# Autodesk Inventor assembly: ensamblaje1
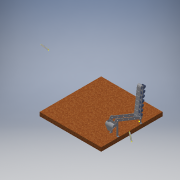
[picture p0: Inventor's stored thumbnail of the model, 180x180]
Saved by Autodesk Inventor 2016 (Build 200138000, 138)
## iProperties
Created: 2016-06
Part Number: ensamblaje1
Document SubType Name: Assembly
Designer: yesi alvarez
Mass: 32615.5 g
Surface Area: 17323.4 cm^2
Volume: 32615.5 cm^3
Density: 1 g/cm^3
Author: yesi alvarez
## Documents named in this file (13)
- C:\Users\adm\Desktop\proyecto del profe. valcarcel\ensamblaje1.iam
- C:\Users\adm\Desktop\proyecto del profe. valcarcel\tablero.ipt
- C:\Users\adm\Desktop\proyecto del profe. valcarcel\soporte1.ipt
- C:\Users\adm\Desktop\proyecto del profe. valcarcel\pieza que une los rodillos.ipt
- C:\Users\adm\Desktop\proyecto del profe. valcarcel\soporte2.ipt
- C:\Users\adm\Desktop\proyecto del profe. valcarcel\rodillo.ipt
- C:\Users\adm\Desktop\proyecto del profe. valcarcel\ensamblaje1\Design Accelerator\Bolted Connection3.iam
- C:\Users\adm\Desktop\proyecto del profe. valcarcel\tuerca.ipt
- C:\Users\adm\Desktop\proyecto del profe. valcarcel\faja2.ipt
- C:\Users\adm\Desktop\Alvarez\cangilogeno.ipt
- C:\Users\adm\Desktop\proyecto del profe. valcarcel\recepcion2.ipt
- C:\Users\adm\Desktop\proyecto del profe. valcarcel\trabajo3\eje.ipt
- C:\Users\adm\Desktop\proyecto del profe. valcarcel\trabajo3\159.iam
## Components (31 placed, 12 different names)
1. tablero:1 — Mate:1, Mate:4, Mate:16, Mate:19, Mate:66, Mate:67, Mate:68, Mate:69, Flush:3
2. soporte1:1 — Mate:1, Mate:2, Mate:3, Mate:20, Mate:21, Mate:44, Mate:45, Mate:46, Mate:57, Flush:2, Mate:68
3. soporte1:2 — Mate:17, Mate:18, Mate:19, Mate:49, Mate:50, Mate:55, Mate:56, Flush:2, Mate:69
4. pieza que une los rodillos:1 — Mate:2, Mate:3, Mate:5, Mate:6, Mate:7
5. pieza que une los rodillos:2 — Mate:13, Mate:14, Mate:15, Mate:17, Mate:18, Mate:65
6. soporte2:1 — Mate:4, Mate:5, Mate:6, Mate:47, Mate:48, Mate:58, Mate:59, Flush:1, Mate:66, Mate:86, Tangent:2
7. soporte2:2 — Mate:14, Mate:15, Mate:16, Mate:51, Mate:52, Mate:53, Mate:54, Flush:1, Mate:67, Flush:3, Mate:84, Mate:85, Tangente:3, Tangente:4
8. rodillo:1 — Mate:7, Mate:13, Mate:65, Flush:4, Flush:12, Tangente:6
9. Bolted Connection:1 [sub-assembly] — Mate:20, Mate:21
10. tuerca:11 — Mate:49, Mate:55
11. tuerca:12 — Mate:52, Mate:53
12. tuerca:13 — Mate:46, Mate:57
13. tuerca:14 — Mate:48, Mate:58
14. tuerca:15 — Mate:51, Mate:54
15. tuerca:16 — Mate:44, Mate:45
16. tuerca:17 — Mate:47, Mate:59
17. tuerca:18 — Mate:50, Mate:56
18. faja2:1 — Flush:4, Mate:70, Mate:71, Flush:5, Mate:72, Mate:73, Mate:74, Mate:75, Mate:76, Flush:6, Flush:7, Flush:8, Flush:9, Flush:10, Mate:77, Mate:78, Mate:79, Mate:80, Mate:81, Mate:82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
19. cangilogeno:1 — Mate:70, Mate:71, Flush:5
20. cangilogeno:2 — Mate:73, Flush:7, Mate:78
21. cangilogeno:3 — Mate:82, Mate:83, Flush:11
22. cangilogeno:4 — Mate:74, Flush:8, Mate:79
23. cangilogeno:5 — Mate:75, Flush:9, Mate:80
24. cangilogeno:6 — Mate:72, Flush:6, Mate:77
25. cangilogeno:7 — Mate:76, Flush:10, Mate:81
26. recepcion2:1 — Mate:84, Mate:85, Mate:86, Mate:87, Insert:2
27. tuerca:19 — Mate:87, Tangent:2
28. tuerca:20 — Insert:2
29. eje:1 — Coincidencia:88, Coincidencia:89, Nivelación:13, Coincidencia:90, Tangente:3, Tangente:4
30. eje:2 — Coincidencia:88, Coincidencia:89, Nivelación:13, Coincidencia:90, Tangente:5
31. 159:1 [sub-assembly]
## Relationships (77: Mate 58, Flush 13, Tangent 5, Insert 1)
- Mate:1: tablero:1 ↔ soporte1:1
- Mate:2: soporte1:1 ↔ pieza que une los rodillos:1
- Mate:3: soporte1:1 ↔ pieza que une los rodillos:1
- Mate:4: tablero:1 ↔ soporte2:1
- Mate:5: pieza que une los rodillos:1 ↔ soporte2:1
- Mate:6: pieza que une los rodillos:1 ↔ soporte2:1
- Mate:7: pieza que une los rodillos:1 ↔ rodillo:1
- Mate:13: pieza que une los rodillos:2 ↔ rodillo:1
- Mate:14: pieza que une los rodillos:2 ↔ soporte2:2
- Mate:15: pieza que une los rodillos:2 ↔ soporte2:2
- Mate:16: tablero:1 ↔ soporte2:2
- Mate:17: soporte1:2 ↔ pieza que une los rodillos:2
- Mate:18: soporte1:2 ↔ pieza que une los rodillos:2
- Mate:19: tablero:1 ↔ soporte1:2
- Mate:20: soporte1:1 ↔ Bolted Connection:1
- Mate:21: soporte1:1 ↔ Bolted Connection:1
- Mate:44: soporte1:1 ↔ tuerca:16
- Mate:45: soporte1:1 ↔ tuerca:16
- Mate:46: soporte1:1 ↔ tuerca:13
- Mate:47: soporte2:1 ↔ tuerca:17
- Mate:48: soporte2:1 ↔ tuerca:14
- Mate:49: soporte1:2 ↔ tuerca:11
- Mate:50: soporte1:2 ↔ tuerca:18
- Mate:51: soporte2:2 ↔ tuerca:15
- Mate:52: soporte2:2 ↔ tuerca:12
- Mate:53: soporte2:2 ↔ tuerca:12
- Mate:54: soporte2:2 ↔ tuerca:15
- Mate:55: soporte1:2 ↔ tuerca:11
- Mate:56: soporte1:2 ↔ tuerca:18
- Mate:57: soporte1:1 ↔ tuerca:13
- Mate:58: soporte2:1 ↔ tuerca:14
- Mate:59: soporte2:1 ↔ tuerca:17
- Mate:65: pieza que une los rodillos:2 ↔ rodillo:1
- Flush:1: soporte2:1 ↔ soporte2:2
- Flush:2: soporte1:1 ↔ soporte1:2
- Mate:66: tablero:1 ↔ soporte2:1
- Mate:67: tablero:1 ↔ soporte2:2
- Mate:68: tablero:1 ↔ soporte1:1
- Mate:69: tablero:1 ↔ soporte1:2
- Flush:3: tablero:1 ↔ soporte2:2
- Flush:4: rodillo:1 ↔ faja2:1
- Mate:70: faja2:1 ↔ cangilogeno:1
- Mate:71: faja2:1 ↔ cangilogeno:1
- Flush:5: faja2:1 ↔ cangilogeno:1
- Mate:72: faja2:1 ↔ cangilogeno:6
- Mate:73: faja2:1 ↔ cangilogeno:2
- Mate:74: faja2:1 ↔ cangilogeno:4
- Mate:75: faja2:1 ↔ cangilogeno:5
- Mate:76: faja2:1 ↔ cangilogeno:7
- Flush:6: faja2:1 ↔ cangilogeno:6
- Flush:7: faja2:1 ↔ cangilogeno:2
- Flush:8: faja2:1 ↔ cangilogeno:4
- Flush:9: faja2:1 ↔ cangilogeno:5
- Flush:10: faja2:1 ↔ cangilogeno:7
- Mate:77: faja2:1 ↔ cangilogeno:6
- Mate:78: faja2:1 ↔ cangilogeno:2
- Mate:79: faja2:1 ↔ cangilogeno:4
- Mate:80: faja2:1 ↔ cangilogeno:5
- Mate:81: faja2:1 ↔ cangilogeno:7
- Mate:82: faja2:1 ↔ cangilogeno:3
- Mate:83: faja2:1 ↔ cangilogeno:3
- Flush:11: faja2:1 ↔ cangilogeno:3
- Flush:12: rodillo:1 ↔ faja2:1
- Mate:84: soporte2:2 ↔ recepcion2:1
- Mate:85: soporte2:2 ↔ recepcion2:1
- Mate:86: soporte2:1 ↔ recepcion2:1
- Mate:87: recepcion2:1 ↔ tuerca:19
- Tangent:2: soporte2:1 ↔ tuerca:19
- Insert:2: recepcion2:1 ↔ tuerca:20
- Coincidencia:88 [Mate]: eje:1 ↔ eje:2
- Coincidencia:89 [Mate]: eje:1 ↔ eje:2
- Nivelación:13 [Flush]: eje:1 ↔ eje:2
- Coincidencia:90 [Mate]: eje:1 ↔ eje:2
- Tangente:3: soporte2:2 ↔ eje:1
- Tangente:4: soporte2:2 ↔ eje:1
- Tangente:5: faja2:1 ↔ eje:2
- Tangente:6: rodillo:1 ↔ faja2:1
